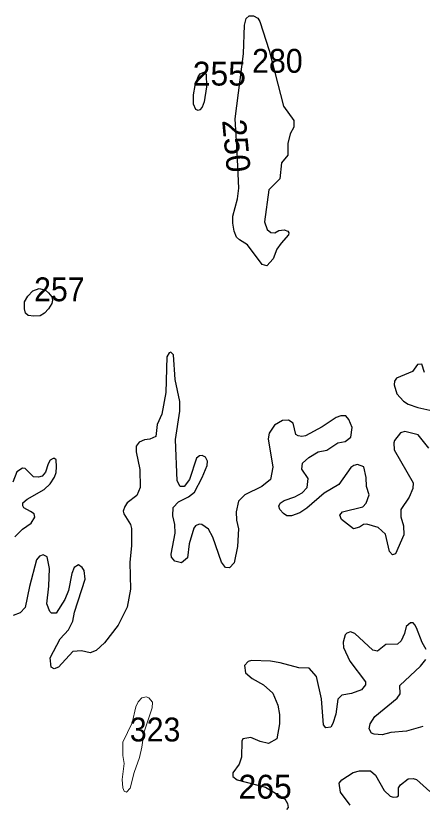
# Model space of a CAD drawing. Extents: x 499.9 to 555.3, y 9281.5 to 9336.8.
# Drawn here: x 503.69 to 506.42, y 9326.31 to 9331.59 of the extents above; entities that cross this region are included whole.
import ezdxf
from ezdxf.enums import TextEntityAlignment as Align

# ---------------------------------------------------------------- set-up
doc = ezdxf.new("R2010")
doc.units = 0
doc.header["$LTSCALE"] = 0.064
doc.layers.add('1', color=7, linetype='Continuous', lineweight=25)
doc.layers.add('2', color=7, linetype='Continuous', lineweight=13)
doc.layers.add('21', color=7, linetype='Continuous')
doc.layers.add('61', color=7, linetype='Continuous')

msp = doc.modelspace()

# ---------------------------------------------------------------- linework, layer by layer
at = {"layer": '1'}
for points in [[(505.1909, 9330.4378), (505.1787, 9330.6793), (505.1673, 9330.9034), (505.223, 9331.3393), (505.2282, 9331.531), (505.2395, 9331.5758), (505.2599, 9331.5942), (505.2899, 9331.593), (505.3188, 9331.5784), (505.3318, 9331.5562), (505.3939, 9331.3617), (505.4914, 9330.9885), (505.5602, 9330.8922), (505.56, 9330.8481), (505.5362, 9330.8026), (505.5191, 9330.7374), (505.5189, 9330.6601), (505.4777, 9330.6076), (505.4663, 9330.5017), (505.3915, 9330.427), (505.3631, 9330.2123), (505.3801, 9330.1612), (505.4061, 9330.1408), (505.4329, 9330.14), (505.4593, 9330.1538), (505.4941, 9330.1587), (505.5198, 9330.1509), (505.5266, 9330.1386), (505.5249, 9330.1254), (505.4739, 9330.0707), (505.4461, 9330.029), (505.4204, 9329.9649), (505.3786, 9329.919), (505.3473, 9329.9277), (505.2486, 9330.058), (505.1949, 9330.0916), (505.1756, 9330.1107), (505.1595, 9330.1502), (505.1498, 9330.2042), (505.1498, 9330.2503), (505.1828, 9330.3667)], [(504.8866, 9331.0009), (504.8867, 9331.0634), (504.8984, 9331.1263), (504.9174, 9331.1853), (504.9308, 9331.2041), (504.9556, 9331.2153), (504.9725, 9331.2024), (504.9737, 9331.1181), (504.9591, 9331.0177), (504.9447, 9330.9823), (504.93, 9330.9636), (504.918, 9330.9597), (504.9018, 9330.9651)], [(503.778, 9329.5844), (503.7609, 9329.6015), (503.7533, 9329.6299), (503.7546, 9329.6767), (503.7758, 9329.7154), (503.81, 9329.7507), (503.8517, 9329.7652), (503.8944, 9329.7549), (503.9152, 9329.7378), (503.938, 9329.7104), (503.9417, 9329.6867), (503.9361, 9329.6659), (503.9152, 9329.6307), (503.8878, 9329.6015), (503.8585, 9329.5833), (503.8168, 9329.5797)]]:
    msp.add_lwpolyline(points, close=True, dxfattribs=at)
for points in [[(505.7494, 9328.8385), (505.6373, 9328.7794), (505.6126, 9328.7731), (505.588, 9328.7776), (505.5728, 9328.7881), (505.5544, 9328.8643), (505.5251, 9328.884), (505.4846, 9328.8805), (505.4307, 9328.8491), (505.3951, 9328.7969), (505.387, 9328.7575), (505.42, 9328.5677), (505.4035, 9328.4857), (505.3452, 9328.4379), (505.2301, 9328.3829), (505.1897, 9328.3396), (505.1721, 9328.2697), (505.1752, 9328.2125), (505.1878, 9328.1543), (505.1825, 9328.0366), (505.1592, 9327.9268), (505.1285, 9327.8924), (505.1021, 9327.896), (505.0758, 9327.9308), (505.0156, 9328.0983), (504.987, 9328.1518), (504.942, 9328.1839), (504.9252, 9328.1851), (504.9012, 9328.1748), (504.8899, 9328.159), (504.8588, 9328.0552), (504.8468, 9327.9612), (504.8057, 9327.928), (504.761, 9327.9376), (504.7395, 9327.9653), (504.7365, 9327.9852), (504.7643, 9328.1265), (504.7626, 9328.1845), (504.7487, 9328.2411), (504.7505, 9328.2982), (504.7853, 9328.3364), (504.8534, 9328.3684), (504.8932, 9328.4004), (504.9455, 9328.4982), (504.9789, 9328.5784), (504.9818, 9328.6093), (504.9685, 9328.6353), (504.946, 9328.6475), (504.9262, 9328.6448), (504.907, 9328.6278), (504.8598, 9328.4863), (504.8234, 9328.4388), (504.7976, 9328.4378), (504.7777, 9328.476), (504.7661, 9328.7535), (504.7962, 9328.9445), (504.7963, 9329.0074), (504.7647, 9329.1555), (504.7522, 9329.3208), (504.7346, 9329.3398), (504.7227, 9329.3343), (504.707, 9329.3071), (504.7017, 9329.068), (504.6736, 9328.9227), (504.6436, 9328.8546), (504.6344, 9328.7736), (504.5934, 9328.7551), (504.5576, 9328.7517), (504.5234, 9328.7353), (504.5023, 9328.7095), (504.5035, 9328.6708), (504.5273, 9328.5522), (504.5287, 9328.4321), (504.5064, 9328.3781), (504.4431, 9328.3284), (504.4257, 9328.3037), (504.415, 9328.2737), (504.42, 9328.2549), (504.4639, 9328.1848), (504.4716, 9328.1563), (504.4716, 9328.0437), (504.4589, 9327.9291), (504.4652, 9327.7508), (504.4428, 9327.63), (504.3819, 9327.5083), (504.2891, 9327.3918), (504.2334, 9327.3393), (504.1946, 9327.3247), (504.1366, 9327.3369), (504.0771, 9327.3318), (503.9823, 9327.2284), (503.9535, 9327.2166), (503.9322, 9327.2265), (503.9261, 9327.29), (503.9937, 9327.4174)], [(506.4369, 9329.2031), (506.4171, 9329.2591), (506.3894, 9329.2566), (506.3552, 9329.2101), (506.2486, 9329.1659), (506.2355, 9329.144), (506.2321, 9329.1196), (506.2508, 9329.06), (506.2956, 9329.0114), (506.3266, 9328.9904), (506.3918, 9328.9683), (506.5128, 9328.941)], [(505.9499, 9328.8331), (505.9293, 9328.8871), (505.9086, 9328.9122), (505.8739, 9328.9126), (505.8429, 9328.901), (505.7494, 9328.8385)], [(506.4642, 9328.6962), (506.3946, 9328.7846), (506.3035, 9328.8071), (506.276, 9328.7988), (506.2356, 9328.7462), (506.2304, 9328.731), (506.2326, 9328.6855), (506.3591, 9328.463), (506.3574, 9328.4257), (506.334, 9328.3661), (506.2766, 9328.2847), (506.2765, 9328.2356), (506.2954, 9328.1742), (506.297, 9328.1146), (506.2426, 9327.9865), (506.2207, 9327.9803), (506.201, 9328.0024), (506.174, 9328.1183), (506.1242, 9328.164), (506.05, 9328.1866), (506.0266, 9328.185), (505.9995, 9328.1664), (505.9608, 9328.1558), (505.8798, 9328.2177), (505.8676, 9328.246), (505.8851, 9328.2679), (506.0217, 9328.3034), (506.0442, 9328.3263), (506.0643, 9328.3819), (506.0475, 9328.4377), (506.0451, 9328.4995), (506.0296, 9328.5694), (505.9875, 9328.5861), (505.962, 9328.5801), (505.9415, 9328.5665), (505.8609, 9328.4528), (505.7633, 9328.3949), (505.6477, 9328.2936), (505.6009, 9328.2631), (505.5451, 9328.2414), (505.5119, 9328.2416), (505.4899, 9328.2577), (505.4652, 9328.2846), (505.4591, 9328.3072), (505.4682, 9328.3266), (505.4958, 9328.3447), (505.5666, 9328.3684), (505.6152, 9328.3951), (505.6491, 9328.4327), (505.6553, 9328.4924), (505.6133, 9328.5557), (505.6175, 9328.5957), (505.6606, 9328.6326), (505.722, 9328.6703), (505.7805, 9328.6824), (505.8556, 9328.7323), (505.9039, 9328.7395), (505.943, 9328.7691), (505.9499, 9328.8331)], [(503.6892, 9328.1015), (503.7396, 9328.1519), (503.7991, 9328.1929), (503.8233, 9328.233), (503.8179, 9328.2555), (503.7933, 9328.2718), (503.7483, 9328.295), (503.7415, 9328.31), (503.743, 9328.3293), (503.7714, 9328.3539), (503.8849, 9328.4183), (503.9251, 9328.4575), (503.9542, 9328.5005), (503.9651, 9328.5322), (503.9687, 9328.5711), (503.9652, 9328.6172), (503.955, 9328.626), (503.9449, 9328.627), (503.9268, 9328.6144), (503.9134, 9328.59), (503.8936, 9328.5338), (503.8712, 9328.5083), (503.8467, 9328.5005), (503.8133, 9328.5045), (503.7583, 9328.5595), (503.7407, 9328.5618), (503.7012, 9328.5372), (503.675, 9328.4683)], [(504.1533, 9327.8756), (504.1393, 9327.8966), (504.1157, 9327.914), (504.0867, 9327.8955), (504.072, 9327.8551), (504.0497, 9327.7414), (504.0243, 9327.6809), (503.9664, 9327.5885), (503.9345, 9327.5902), (503.9234, 9327.6015), (503.9037, 9327.6523), (503.9177, 9327.7699), (503.9208, 9327.8889), (503.9067, 9327.9681), (503.878, 9327.9812), (503.8548, 9327.9707), (503.8351, 9327.9465), (503.7871, 9327.7691), (503.7587, 9327.6274), (503.7249, 9327.5911), (503.6767, 9327.5733)], [(503.9937, 9327.4174), (504.0481, 9327.4772), (504.0781, 9327.5369), (504.0883, 9327.5957), (504.1594, 9327.8178), (504.1533, 9327.8756)], [(506.448, 9327.3465), (506.4204, 9327.3931), (506.3816, 9327.4904), (506.3715, 9327.5123), (506.3601, 9327.5248), (506.3428, 9327.5242), (506.3122, 9327.4998), (506.3014, 9327.4542), (506.2799, 9327.4035), (506.2559, 9327.3824), (506.1778, 9327.3797), (506.1219, 9327.3343), (506.0889, 9327.3408), (505.9693, 9327.4538), (505.9407, 9327.4638), (505.9143, 9327.4565), (505.903, 9327.4433), (505.8917, 9327.3962), (505.8933, 9327.3594), (505.9344, 9327.2671), (506.0393, 9327.129), (506.0407, 9327.1101), (506.0145, 9327.0759), (505.9454, 9327.0506), (505.8826, 9327.0394), (505.8539, 9327.0128), (505.8413, 9326.9117), (505.8212, 9326.8501), (505.8068, 9326.8259), (505.7737, 9326.8203), (505.7582, 9326.8399), (505.7448, 9327.0155), (505.7123, 9327.1657), (505.6624, 9327.2217), (505.5944, 9327.2227), (505.4679, 9327.2574), (505.4034, 9327.2686), (505.2763, 9327.2715), (505.2542, 9327.2648), (505.2296, 9327.2397), (505.2348, 9327.1902), (505.2802, 9327.1509), (505.3564, 9327.1093), (505.4179, 9327.0542), (505.4524, 9326.9722), (505.4647, 9326.9097), (505.4647, 9326.8477), (505.4453, 9326.7468), (505.3891, 9326.7165), (505.3341, 9326.7296), (505.2725, 9326.7563), (505.2184, 9326.7478), (505.21, 9326.7319), (505.2085, 9326.6245), (505.1921, 9326.5779), (505.1502, 9326.5182), (505.1502, 9326.494), (505.1808, 9326.4714)], [(506.4253, 9326.8306), (506.3146, 9326.7992), (506.2102, 9326.7901), (506.1515, 9326.7738), (506.0991, 9326.7784), (506.0804, 9326.7856), (506.0651, 9326.8135), (506.0706, 9326.847), (506.1034, 9326.8962), (506.2535, 9327.0198), (506.2728, 9327.049), (506.2696, 9327.1057), (506.4101, 9327.2352), (506.4448, 9327.2799)], [(505.937, 9326.3016), (505.8727, 9326.3895), (505.8628, 9326.4489), (505.8809, 9326.4732), (505.9567, 9326.522), (506.0002, 9326.5321), (506.0728, 9326.5335), (506.1072, 9326.5045), (506.1649, 9326.3999), (506.205, 9326.3634), (506.2252, 9326.3555), (506.2505, 9326.3586), (506.2614, 9326.365), (506.2624, 9326.4184), (506.2755, 9326.4382), (506.326, 9326.4781), (506.3609, 9326.482), (506.3831, 9326.4747), (506.4723, 9326.3934)], [(505.1808, 9326.4714), (505.369, 9326.4238), (505.499, 9326.3441), (505.5181, 9326.3143), (505.5211, 9326.2861), (505.5109, 9326.2736)]]:
    msp.add_lwpolyline(points, dxfattribs=at)
at = {"layer": '2'}
msp.add_lwpolyline([(504.4213, 9326.5829), (504.4121, 9326.6356), (504.4122, 9326.7241), (504.4757, 9326.8534), (504.5002, 9326.9608), (504.5167, 9326.9945), (504.5411, 9327.0212), (504.5688, 9327.0296), (504.5868, 9327.0213), (504.6125, 9326.9937), (504.6098, 9326.9544), (504.5528, 9326.7863), (504.5414, 9326.6902), (504.5253, 9326.6224), (504.4895, 9326.5207), (504.4624, 9326.4156), (504.4376, 9326.3891), (504.422, 9326.3957), (504.4122, 9326.4197), (504.408, 9326.4744)], close=True, dxfattribs=at)

# ---------------------------------------------------------------- texts
at = {"layer": '21', "width": 0.95}
for s, p in [('280', (505.28, 9331.212)), ('257', (503.8179, 9329.6804)), ('323', (504.4598, 9326.7297))]:
    msp.add_text(s, height=0.16, dxfattribs=at).set_placement(p)
at = {"layer": '21'}
for s, p in [('255', (504.8817, 9331.1263)), ('265', (505.1888, 9326.3462))]:
    msp.add_text(s, height=0.16, dxfattribs=at).set_placement(p)
at = {"layer": '61'}
msp.add_text('250', height=0.16, rotation=275.38, dxfattribs=at).set_placement((505.0949, 9330.7154), align=Align.CENTER)

doc.saveas('drawing.dxf')
